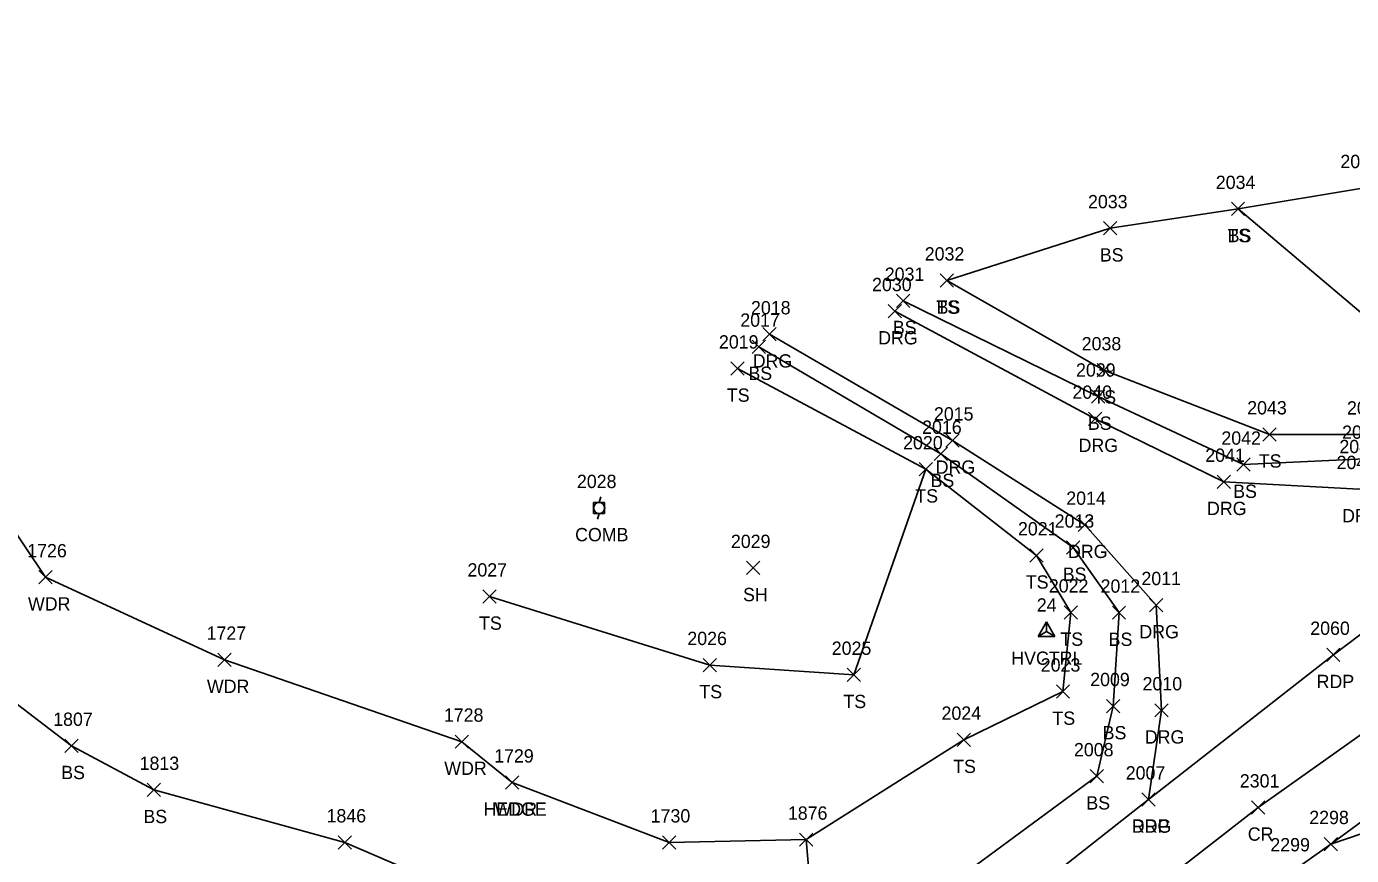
# Model space of a CAD drawing. Extents: x 1505656 to 1508446, y 700805 to 703031.
# Drawn here: x 1506624.7 to 1506823.9, y 702293 to 702417.6 of the extents above; entities that cross this region are included whole.
import ezdxf

# ---------------------------------------------------------------- set-up
doc = ezdxf.new("R2010")
doc.units = 0
for name, color, linetype in [('C_A', 7, 'Continuous'), ('C_I', 7, 'Continuous'), ('CPSM', 7, 'Continuous'), ('L_A', 7, 'Continuous'), ('L_I', 7, 'Continuous'), ('L_TIC', 7, 'Continuous'), ('LAHR', 7, 'Continuous'), ('LAWA', 7, 'Continuous'), ('LELB', 7, 'Continuous'), ('P_A', 7, 'Continuous'), ('P_I', 7, 'Continuous'), ('P_TIC', 7, 'Continuous'), ('PET', 7, 'Continuous'), ('PRC', 7, 'Continuous'), ('R_A', 7, 'Continuous'), ('R_I', 7, 'Continuous'), ('R_TIC', 7, 'Continuous'), ('RDG', 7, 'Continuous'), ('U_A', 7, 'Continuous'), ('U_I', 7, 'Continuous'), ('UP', 7, 'Continuous')]:
    doc.layers.add(name, color=color, linetype=linetype)

msp = doc.modelspace()

# ---------------------------------------------------------------- linework, layer by layer
at = {"layer": 'CPSM'}
for p, q in [((1506776.83, 702325.89), (1506778.08, 702328.05)), ((1506779.33, 702325.89), (1506778.08, 702328.05)), ((1506778.08, 702326.61), (1506778.08, 702328.05)), ((1506776.83, 702325.89), (1506778.08, 702326.61)), ((1506776.83, 702325.89), (1506779.33, 702325.89)), ((1506778.08, 702326.61), (1506778.08, 702326.61)), ((1506778.08, 702326.61), (1506779.33, 702325.89))]:
    msp.add_line(p, q, dxfattribs=at)
at = {"layer": 'L_TIC'}
for points in [[(1506805.86, 702389.13), (1506807.86, 702391.13)], [(1506807.86, 702389.13), (1506805.86, 702391.13)], [(1506805.86, 702389.13), (1506807.86, 702391.13)], [(1506807.86, 702389.13), (1506805.86, 702391.13)], [(1506786.64, 702386.23), (1506788.64, 702388.23)], [(1506788.64, 702386.23), (1506786.64, 702388.23)], [(1506762.11, 702378.38), (1506764.11, 702380.38)], [(1506764.11, 702378.38), (1506762.11, 702380.38)], [(1506762.11, 702378.38), (1506764.11, 702380.38)], [(1506764.11, 702378.38), (1506762.11, 702380.38)], [(1506755.53, 702375.32), (1506757.53, 702377.32)], [(1506757.53, 702375.32), (1506755.53, 702377.32)], [(1506733.82, 702368.43), (1506735.82, 702370.43)], [(1506735.82, 702368.43), (1506733.82, 702370.43)], [(1506730.61, 702365.15), (1506732.61, 702367.15)], [(1506732.61, 702365.15), (1506730.61, 702367.15)], [(1506785.7, 702364.88), (1506787.7, 702366.88)], [(1506787.7, 702364.88), (1506785.7, 702366.88)], [(1506784.86, 702360.93), (1506786.86, 702362.93)], [(1506786.86, 702360.93), (1506784.86, 702362.93)], [(1506810.58, 702355.25), (1506812.58, 702357.25)], [(1506812.58, 702355.25), (1506810.58, 702357.25)], [(1506761.2, 702352.33), (1506763.2, 702354.33)], [(1506763.2, 702352.33), (1506761.2, 702354.33)], [(1506806.7, 702350.7), (1506808.7, 702352.7)], [(1506808.7, 702350.7), (1506806.7, 702352.7)], [(1506758.95, 702350), (1506760.95, 702352)], [(1506760.95, 702350), (1506758.95, 702352)], [(1506758.95, 702350), (1506760.95, 702352)], [(1506760.95, 702350), (1506758.95, 702352)], [(1506775.55, 702337.06), (1506777.55, 702339.06)], [(1506777.55, 702337.06), (1506775.55, 702339.06)], [(1506781.07, 702338.23), (1506783.07, 702340.23)], [(1506783.07, 702338.23), (1506781.07, 702340.23)], [(1506732.97, 702335.17), (1506734.97, 702337.17)], [(1506734.97, 702335.17), (1506732.97, 702337.17)], [(1506626.6, 702333.77), (1506628.6, 702335.77)], [(1506628.6, 702333.77), (1506626.6, 702335.77)], [(1506693.36, 702330.88), (1506695.36, 702332.88)], [(1506695.36, 702330.88), (1506693.36, 702332.88)], [(1506780.75, 702328.47), (1506782.75, 702330.47)], [(1506782.75, 702328.47), (1506780.75, 702330.47)], [(1506787.97, 702328.45), (1506789.97, 702330.45)], [(1506789.97, 702328.45), (1506787.97, 702330.45)], [(1506653.5, 702321.38), (1506655.5, 702323.38)], [(1506655.5, 702321.38), (1506653.5, 702323.38)], [(1506726.48, 702320.58), (1506728.48, 702322.58)], [(1506728.48, 702320.58), (1506726.48, 702322.58)], [(1506748.13, 702319.11), (1506750.13, 702321.11)], [(1506750.13, 702319.11), (1506748.13, 702321.11)], [(1506779.55, 702316.59), (1506781.55, 702318.59)], [(1506781.55, 702316.59), (1506779.55, 702318.59)], [(1506787.07, 702314.41), (1506789.07, 702316.41)], [(1506789.07, 702314.41), (1506787.07, 702316.41)], [(1506689.18, 702309.06), (1506691.18, 702311.06)], [(1506691.18, 702309.06), (1506689.18, 702311.06)], [(1506764.63, 702309.35), (1506766.63, 702311.35)], [(1506766.63, 702309.35), (1506764.63, 702311.35)], [(1506764.63, 702309.35), (1506766.63, 702311.35)], [(1506766.63, 702309.35), (1506764.63, 702311.35)], [(1506630.52, 702308.43), (1506632.52, 702310.43)], [(1506632.52, 702308.43), (1506630.52, 702310.43)], [(1506696.74, 702302.92), (1506698.74, 702304.92)], [(1506698.74, 702302.92), (1506696.74, 702304.92)], [(1506696.74, 702302.92), (1506698.74, 702304.92)], [(1506698.74, 702302.92), (1506696.74, 702304.92)], [(1506784.62, 702303.86), (1506786.62, 702305.86)], [(1506786.62, 702303.86), (1506784.62, 702305.86)], [(1506642.87, 702301.81), (1506644.87, 702303.81)], [(1506644.87, 702301.81), (1506642.87, 702303.81)], [(1506671.58, 702293.92), (1506673.58, 702295.92)], [(1506673.58, 702293.92), (1506671.58, 702295.92)], [(1506720.35, 702293.91), (1506722.35, 702295.91)], [(1506722.35, 702293.91), (1506720.35, 702295.91)], [(1506720.35, 702293.91), (1506722.35, 702295.91)], [(1506722.35, 702293.91), (1506720.35, 702295.91)], [(1506740.94, 702294.33), (1506742.94, 702296.33)], [(1506742.94, 702294.33), (1506740.94, 702296.33)], [(1506740.94, 702294.33), (1506742.94, 702296.33)], [(1506742.94, 702294.33), (1506740.94, 702296.33)], [(1506740.94, 702294.33), (1506742.94, 702296.33)], [(1506742.94, 702294.33), (1506740.94, 702296.33)], [(1506819.83, 702293.67), (1506821.83, 702295.67)], [(1506821.83, 702293.67), (1506819.83, 702295.67)]]:
    msp.add_lwpolyline(points, dxfattribs=at)
at = {"layer": 'LAHR'}
msp.add_lwpolyline([(1506697.74, 702303.92), (1506721.35, 702294.91)], dxfattribs=at)
at = {"layer": 'LAWA'}
for points in [[(1506568.32, 702421.69), (1506587.29, 702397.28), (1506601.28, 702378.92), (1506614.7, 702353.95), (1506627.6, 702334.77), (1506654.5, 702322.38), (1506690.18, 702310.06), (1506697.74, 702303.92)], [(1506477.11, 702338.78), (1506505.06, 702319.4), (1506519.83, 702306.48), (1506544.92, 702278.68), (1506587.97, 702243.37), (1506602.7, 702221.47), (1506611.67, 702210.59), (1506619.38, 702208.31), (1506641.95, 702218.05), (1506645.77, 702210.36), (1506641.46, 702203.26), (1506655.95, 702212.94), (1506663.5, 702213.58), (1506668.03, 702215.72), (1506670.93, 702221.58), (1506675.61, 702223.42), (1506692.94, 702236.13), (1506718.23, 702260.42), (1506729.5, 702264.44), (1506742.86, 702284.75), (1506741.94, 702295.33)], [(1506721.35, 702294.91), (1506741.94, 702295.33)]]:
    msp.add_lwpolyline(points, dxfattribs=at)
at = {"layer": 'LELB'}
for points in [[(1506554.73, 702410.63), (1506571.62, 702388.81), (1506587.3, 702364.68), (1506595.49, 702347.32), (1506603.05, 702331.19), (1506631.52, 702309.43), (1506643.87, 702302.81), (1506672.58, 702294.92), (1506695.6, 702285.04), (1506708.11, 702283.35), (1506723.52, 702281.47), (1506742.86, 702284.75), (1506754.22, 702281.75), (1506785.62, 702304.86), (1506788.07, 702315.41), (1506788.97, 702329.45), (1506782.07, 702339.23), (1506762.2, 702353.33), (1506734.82, 702369.43)], [(1506806.86, 702390.13), (1506825.59, 702393.27), (1506837.69, 702373.61), (1506847.65, 702361.17), (1506861.89, 702370.19), (1506887.92, 702381.43), (1506891.18, 702375.73), (1506887.69, 702371.57)], [(1506763.11, 702379.38), (1506787.64, 702387.23), (1506806.86, 702390.13), (1506829.87, 702370.72), (1506837.67, 702358.99), (1506846.99, 702356.14), (1506850.47, 702356.32), (1506864.89, 702364.44), (1506883.68, 702375.24)], [(1506763.11, 702379.38), (1506786.7, 702365.88), (1506811.58, 702356.25), (1506826.58, 702356.23), (1506837.67, 702358.99), (1506847.65, 702361.17), (1506846.99, 702356.14), (1506848.24, 702353.58), (1506852.76, 702352.08), (1506867.59, 702359.54), (1506887.69, 702371.57)], [(1506756.53, 702376.32), (1506785.86, 702361.93), (1506807.7, 702351.7), (1506825.85, 702352.58), (1506838.85, 702351.49), (1506848.24, 702353.58), (1506851.3, 702355.42), (1506865.79, 702362.8), (1506885.52, 702373.02), (1506888.66, 702376.33), (1506887.72, 702377.3), (1506883.68, 702375.24)], [(1506731.61, 702366.15), (1506759.95, 702351), (1506776.55, 702338.06), (1506781.75, 702329.47), (1506780.55, 702317.59), (1506765.63, 702310.35)], [(1506759.95, 702351), (1506749.13, 702320.11), (1506727.48, 702321.58), (1506694.36, 702331.88)], [(1506882.18, 702328.96), (1506860.02, 702317.38), (1506846.48, 702309.07), (1506828.05, 702297.1), (1506820.83, 702294.67)], [(1506741.94, 702295.33), (1506765.63, 702310.35)]]:
    msp.add_lwpolyline(points, dxfattribs=at)
at = {"layer": 'P_TIC'}
for points in [[(1506820.19, 702322.11), (1506822.19, 702324.11)], [(1506822.19, 702322.11), (1506820.19, 702324.11)], [(1506792.4, 702300.37), (1506794.4, 702302.37)], [(1506794.4, 702300.37), (1506792.4, 702302.37)], [(1506808.9, 702299.17), (1506810.9, 702301.17)], [(1506810.9, 702299.17), (1506808.9, 702301.17)], [(1506819.83, 702293.67), (1506821.83, 702295.67)], [(1506821.83, 702293.67), (1506819.83, 702295.67)]]:
    msp.add_lwpolyline(points, dxfattribs=at)
at = {"layer": 'PET'}
for points in [[(1506450.65, 702029.2), (1506459.01, 702027.77), (1506468.15, 702029.49), (1506475.63, 702033.45), (1506492.49, 702050.17), (1506507, 702065.69), (1506526.03, 702085.92), (1506543.4, 702101.89), (1506555.15, 702112.06), (1506575.48, 702129.8), (1506589.02, 702140.73), (1506620.87, 702167.68), (1506653.75, 702193.6), (1506674.56, 702208.99), (1506700.97, 702228.57), (1506728, 702249.61), (1506759.67, 702274.83), (1506793.4, 702301.37), (1506821.19, 702323.11), (1506840.12, 702337.4)], [(1506857.05, 702321.26), (1506820.83, 702294.67), (1506814.99, 702290.57), (1506777.85, 702262.75), (1506747.99, 702238.85), (1506725.92, 702221.9), (1506702.36, 702203.8), (1506679.15, 702185.98), (1506669.5, 702178.34), (1506637.66, 702153.48), (1506604.91, 702127), (1506574.06, 702100.19), (1506542.07, 702070.61), (1506522.55, 702050.29), (1506506.91, 702029.72), (1506498.07, 702013.24), (1506495.48, 702000.5), (1506496.78, 701989.17), (1506504.12, 701976.85)]]:
    msp.add_lwpolyline(points, dxfattribs=at)
at = {"layer": 'PRC'}
msp.add_lwpolyline([(1507099.79, 702434.29), (1507054.12, 702415.31), (1507012.5, 702399.89), (1506976.2, 702386.69), (1506932.66, 702370.41), (1506907.47, 702359.22), (1506868.1, 702338.86), (1506842.67, 702323.4), (1506809.9, 702300.17), (1506770.28, 702269.35), (1506742.25, 702247.51), (1506720.16, 702229.85), (1506696, 702211.38), (1506672.48, 702193.19), (1506662.62, 702185.62), (1506629.64, 702159.4), (1506597.85, 702133.73), (1506566.79, 702107.87), (1506534.18, 702078.28), (1506512.18, 702055.63), (1506496.34, 702038.07), (1506482, 702021.83), (1506469.42, 702008.91)], dxfattribs=at)
at = {"layer": 'R_TIC'}
for points in [[(1506754.28, 702373.77), (1506756.28, 702375.77)], [(1506756.28, 702373.77), (1506754.28, 702375.77)], [(1506735.42, 702370.29), (1506737.42, 702372.29)], [(1506737.42, 702370.29), (1506735.42, 702372.29)], [(1506784.4, 702357.6), (1506786.4, 702359.6)], [(1506786.4, 702357.6), (1506784.4, 702359.6)], [(1506762.92, 702354.33), (1506764.92, 702356.33)], [(1506764.92, 702354.33), (1506762.92, 702356.33)], [(1506803.71, 702348.12), (1506805.71, 702350.12)], [(1506805.71, 702348.12), (1506803.71, 702350.12)], [(1506782.81, 702341.66), (1506784.81, 702343.66)], [(1506784.81, 702341.66), (1506782.81, 702343.66)], [(1506793.54, 702329.59), (1506795.54, 702331.59)], [(1506795.54, 702329.59), (1506793.54, 702331.59)], [(1506794.36, 702313.77), (1506796.36, 702315.77)], [(1506796.36, 702313.77), (1506794.36, 702315.77)], [(1506792.4, 702300.37), (1506794.4, 702302.37)], [(1506794.4, 702300.37), (1506792.4, 702302.37)]]:
    msp.add_lwpolyline(points, dxfattribs=at)
at = {"layer": 'RDG'}
for points in [[(1506755.28, 702374.77), (1506785.4, 702358.6), (1506804.71, 702349.12), (1506825.02, 702348.03), (1506837.53, 702348.6), (1506848.28, 702349.21), (1506862.01, 702351.33)], [(1506793.4, 702301.37), (1506795.36, 702314.77), (1506794.54, 702330.59), (1506783.81, 702342.66), (1506763.92, 702355.33), (1506736.42, 702371.29)]]:
    msp.add_lwpolyline(points, dxfattribs=at)
at = {"layer": 'UP'}
for p, q in [((1506711.07, 702346.84), (1506710.82, 702346.01)), ((1506709.99, 702344.34), (1506709.99, 702346.01)), ((1506709.99, 702346.01), (1506711.65, 702346.01)), ((1506710.82, 702345.18), (1506710.82, 702345.18)), ((1506711.65, 702346.01), (1506711.65, 702344.34)), ((1506711.65, 702344.34), (1506709.99, 702344.34)), ((1506710.57, 702343.51), (1506710.82, 702344.34))]:
    msp.add_line(p, q, dxfattribs=at)
msp.add_circle((1506710.82, 702345.18), 0.833, dxfattribs=at)

# ---------------------------------------------------------------- texts
at = {"layer": 'C_A'}
msp.add_text('HVCTRL', height=2, dxfattribs=at).set_placement((1506772.77, 702321.61))
at = {"layer": 'C_I'}
msp.add_text('24', height=2, dxfattribs=at).set_placement((1506776.61, 702329.61))
at = {"layer": 'L_A'}
for s, p in [('TS', (1506805.27, 702385.13)), ('BS', (1506805.3, 702385.13)), ('BS', (1506786.08, 702382.23)), ('TS', (1506761.52, 702374.38)), ('BS', (1506761.55, 702374.38)), ('BS', (1506754.97, 702371.32)), ('BS', (1506733.26, 702364.43)), ('TS', (1506730.02, 702361.15)), ('TS', (1506785.11, 702360.88)), ('BS', (1506784.3, 702356.93)), ('TS', (1506809.99, 702351.25)), ('BS', (1506760.64, 702348.33)), ('BS', (1506806.14, 702346.7)), ('TS', (1506758.35, 702346)), ('TS', (1506758.35, 702346)), ('TS', (1506774.96, 702333.06)), ('BS', (1506780.51, 702334.23)), ('SH', (1506732.46, 702331.17)), ('WDR', (1506624.96, 702329.77)), ('TS', (1506692.77, 702326.88)), ('TS', (1506780.16, 702324.47)), ('BS', (1506787.41, 702324.45)), ('WDR', (1506651.86, 702317.38)), ('TS', (1506725.89, 702316.58)), ('TS', (1506747.54, 702315.11)), ('TS', (1506778.96, 702312.59)), ('BS', (1506786.51, 702310.41)), ('WDR', (1506687.54, 702305.06)), ('TS', (1506764.04, 702305.35)), ('TS', (1506764.04, 702305.35)), ('BS', (1506629.96, 702304.43)), ('HEDGE', (1506693.44, 702298.92)), ('WDR', (1506695.1, 702298.92)), ('BS', (1506784.06, 702299.86)), ('BS', (1506642.31, 702297.81))]:
    msp.add_text(s, height=2, dxfattribs=at).set_placement(p)
at = {"layer": 'L_I'}
for s, p in [('2035', (1506822.25, 702396.27)), ('2035', (1506822.25, 702396.27)), ('2034', (1506803.52, 702393.13)), ('2034', (1506803.52, 702393.13)), ('2033', (1506784.31, 702390.23)), ('2032', (1506759.77, 702382.38)), ('2032', (1506759.77, 702382.38)), ('2031', (1506753.76, 702379.32)), ('2017', (1506732.04, 702372.43)), ('2019', (1506728.83, 702369.15)), ('2038', (1506783.36, 702368.88)), ('2039', (1506782.51, 702364.93)), ('2043', (1506808.24, 702359.25)), ('2044', (1506823.24, 702359.23)), ('2016', (1506759.37, 702356.33)), ('2042', (1506804.36, 702354.7)), ('2045', (1506822.51, 702355.58)), ('2020', (1506756.52, 702354)), ('2020', (1506756.52, 702354)), ('2046', (1506822.1, 702353.42)), ('2021', (1506773.78, 702341.06)), ('2013', (1506779.3, 702342.23)), ('2029', (1506730.63, 702339.17)), ('1726', (1506624.85, 702337.77)), ('2027', (1506691.03, 702334.88)), ('2022', (1506778.42, 702332.47)), ('2012', (1506786.2, 702332.45)), ('1727', (1506651.81, 702325.38)), ('2026', (1506724.08, 702324.58)), ('2025', (1506745.79, 702323.11)), ('2023', (1506777.21, 702320.59)), ('2009', (1506784.64, 702318.41)), ('1728', (1506687.48, 702313.06)), ('2024', (1506762.29, 702313.35)), ('2024', (1506762.29, 702313.35)), ('1807', (1506628.75, 702312.43)), ('1729', (1506695.04, 702306.92)), ('1729', (1506695.04, 702306.92)), ('2008', (1506782.2, 702307.86)), ('1813', (1506641.74, 702305.81)), ('1846', (1506669.84, 702297.92)), ('1730', (1506718.57, 702297.91)), ('1730', (1506718.57, 702297.91)), ('1876', (1506739.19, 702298.33)), ('1876', (1506739.19, 702298.33)), ('1876', (1506739.19, 702298.33)), ('2298', (1506817.57, 702297.67)), ('2299', (1506811.72, 702293.57))]:
    msp.add_text(s, height=2, dxfattribs=at).set_placement(p)
at = {"layer": 'P_A'}
for s, p in [('RDP', (1506818.68, 702318.11)), ('RDP', (1506790.89, 702296.37)), ('CR', (1506808.33, 702295.17))]:
    msp.add_text(s, height=2, dxfattribs=at).set_placement(p)
at = {"layer": 'P_I'}
for s, p in [('2060', (1506817.72, 702326.11)), ('2007', (1506789.98, 702304.37)), ('2301', (1506807.13, 702303.17)), ('2298', (1506817.57, 702297.67)), ('2299', (1506811.72, 702293.57))]:
    msp.add_text(s, height=2, dxfattribs=at).set_placement(p)
at = {"layer": 'R_A'}
for p in [(1506752.77, 702369.77), (1506733.91, 702366.29), (1506782.89, 702353.6), (1506761.41, 702350.33), (1506802.2, 702344.12), (1506822.5, 702343.03), (1506781.3, 702337.66), (1506792.03, 702325.59), (1506792.85, 702309.77), (1506790.89, 702296.37)]:
    msp.add_text('DRG', height=2, dxfattribs=at).set_placement(p)
at = {"layer": 'R_I'}
for s, p in [('2030', (1506751.85, 702377.77)), ('2018', (1506733.65, 702374.29)), ('2040', (1506781.97, 702361.6)), ('2015', (1506761.15, 702358.33)), ('2041', (1506801.94, 702352.12)), ('2047', (1506821.68, 702351.03)), ('2014', (1506781.04, 702345.66)), ('2011', (1506792.34, 702333.59)), ('2010', (1506792.51, 702317.77)), ('2007', (1506789.98, 702304.37))]:
    msp.add_text(s, height=2, dxfattribs=at).set_placement(p)
at = {"layer": 'U_A'}
msp.add_text('COMB', height=2, dxfattribs=at).set_placement((1506707.21, 702340.18))
at = {"layer": 'U_I'}
msp.add_text('2028', height=2, dxfattribs=at).set_placement((1506707.48, 702348.18))

doc.saveas('drawing.dxf')
